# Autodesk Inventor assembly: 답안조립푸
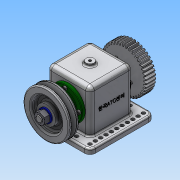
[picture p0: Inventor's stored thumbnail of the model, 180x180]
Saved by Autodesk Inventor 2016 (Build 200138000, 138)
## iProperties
Created: 2018-11
Part Number: 답안조립푸
Material: 일반
Document SubType Name: Assembly
Designer: Administrator
Author: Administrator
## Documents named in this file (13)
- C:\Users\Administrator\Desktop\481107V1003\답안조립품.iam
- C:\Users\Administrator\Desktop\481107V1003\본체.ipt
- C:\Users\Administrator\Desktop\481107V1003\축.ipt
- C:\Users\Administrator\Desktop\481107V1003\베어링 6203.ipt
- C:\Users\Administrator\Desktop\481107V1003\커버.ipt
- C:\Users\Administrator\Desktop\481107V1003\오일 실 26 38 8.ipt
- C:\Users\Administrator\Desktop\481107V1003\키 5x5x12.ipt
- C:\Users\Administrator\Desktop\481107V1003\볼트 M4.ipt
- C:\Users\Administrator\Desktop\481107V1003\부시.ipt
- C:\Users\Administrator\Desktop\481107V1003\V벨트풀리.ipt
- C:\Users\Administrator\Desktop\481107V1003\와셔 12x24.ipt
- C:\Users\Administrator\Desktop\481107V1003\너트 M12x1.25.ipt
- C:\Users\Administrator\Desktop\481107V1003\스퍼기어.ipt
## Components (1 placed, 1 different names)
1. V벨트풀리:1
